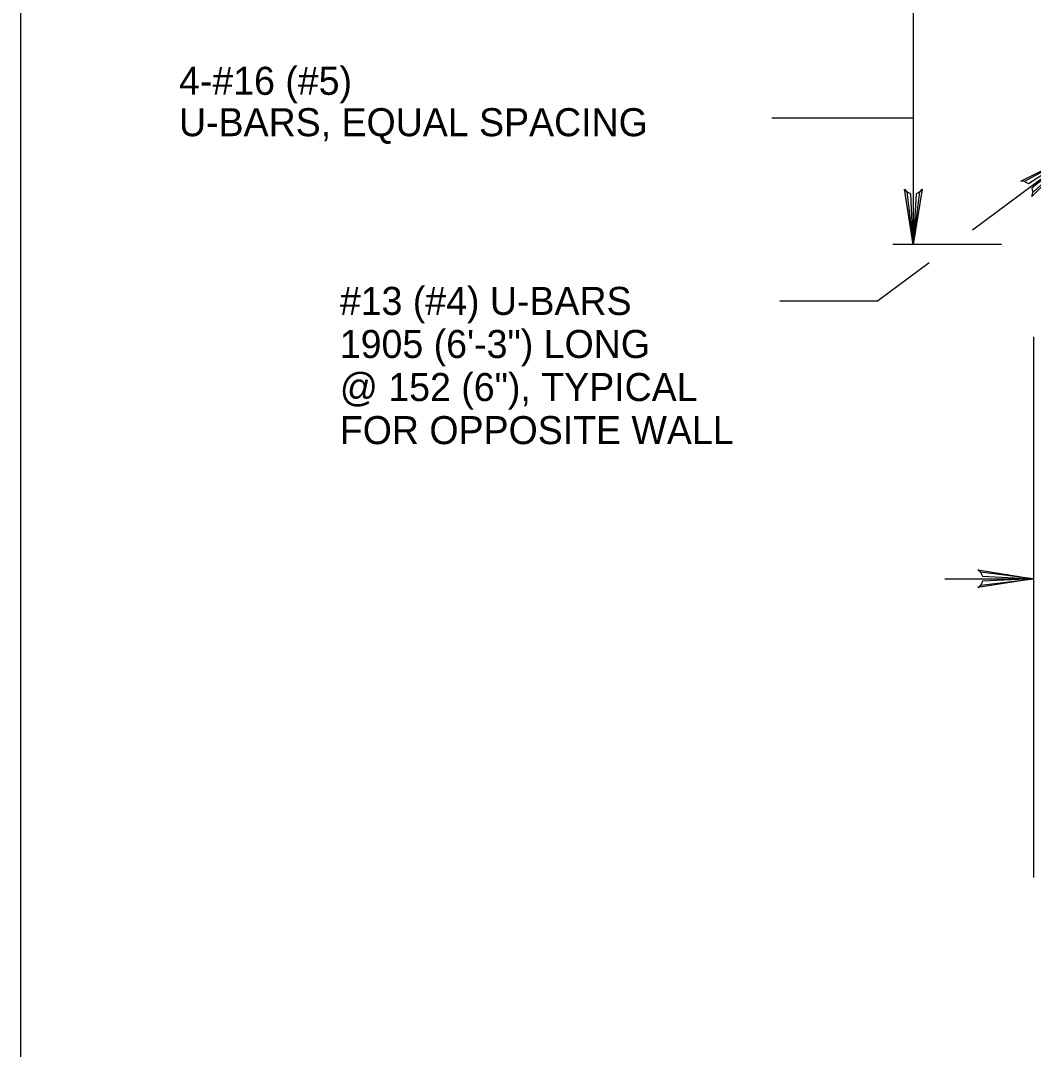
# Model space of a CAD drawing. Extents: x 638455 to 640199, y 298558 to 299152.
# Drawn here: x 639333.6 to 639455, y 298856.5 to 298979.8 of the extents above; entities that cross this region are included whole.
import ezdxf

# ---------------------------------------------------------------- set-up
doc = ezdxf.new("R2010")
doc.units = 0
for name, color, linetype in [('1', 7, 'Continuous'), ('2', 7, 'Continuous'), ('3', 7, 'Continuous')]:
    doc.layers.add(name, color=color, linetype=linetype)

msp = doc.modelspace()

# ---------------------------------------------------------------- linework, layer by layer
at = {"layer": '1'}
for points in [[(640119.61, 298573.25), (640119.61, 299137.25), (639333.61, 299137.25), (639333.61, 298573.25), (640119.61, 298573.25), (640119.61, 298599.61), (639919.61, 298599.61), (639919.61, 298664.29), (640119.61, 298664.29), (640119.61, 298693.25), (639919.61, 298693.25), (639919.61, 298573.25), (639998.42, 298573.25), (639998.42, 298599.61), (639998.42, 298573.25), (640075.42, 298573.25), (640075.42, 298599.61), (640075.42, 298587.29), (640119.61, 298587.29)], [(639453.92, 298960.48), (639454.41, 298960.24), (639459.83, 298963.74), (639453.92, 298960.48), (639453.47, 298960.52), (639459.83, 298963.74), (639454.81, 298959.69), (639454.9, 298959.17), (639459.83, 298963.74), (639454.8, 298958.69), (639454.9, 298959.17)]]:
    msp.add_lwpolyline(points, dxfattribs=at)
at = {"layer": '2'}
for p, q in [((639440.59, 299066.59), (639440.59, 298952.92)), ((639423.64, 298968.1), (639440.59, 298968.1)), ((639447.69, 298954.68), (639459.83, 298963.74)), ((639451.15, 298952.92), (639438.15, 298952.92)), ((639436.28, 298946.17), (639442.48, 298950.79)), ((639424.58, 298946.17), (639436.28, 298946.17)), ((639454.98, 298941.89), (639454.98, 298877.08)), ((639444.36, 298912.89), (639454.98, 298912.89))]:
    msp.add_line(p, q, dxfattribs=at)
for points in [[(639441.38, 298959.25), (639440.92, 298959.02), (639440.59, 298952.92), (639441.38, 298959.25), (639441.66, 298959.58), (639440.59, 298952.92), (639440.28, 298959.01), (639439.83, 298959.23), (639440.59, 298952.92), (639439.53, 298959.58), (639439.83, 298959.23)], [(639448.65, 298913.68), (639448.89, 298913.22), (639454.98, 298912.89), (639448.65, 298913.68), (639448.33, 298913.96), (639454.98, 298912.89), (639448.89, 298912.59), (639448.67, 298912.13), (639454.98, 298912.89), (639448.33, 298911.83), (639448.67, 298912.13)]]:
    msp.add_lwpolyline(points, dxfattribs=at)

# ---------------------------------------------------------------- texts
at = {"layer": '3'}
for s, p in [('4-#16 (#5)', (639352.6, 298970.87)), ('U-BARS, EQUAL SPACING', (639352.6, 298965.91)), ('#13 (#4) U-BARS', (639371.87, 298944.5)), ('1905 (6\'-3") LONG', (639371.87, 298939.34)), ('@ 152 (6"), TYPICAL', (639371.87, 298934.18)), ('FOR OPPOSITE WALL', (639371.87, 298929.02))]:
    msp.add_text(s, height=3.36, dxfattribs=at).set_placement(p)

doc.saveas('drawing.dxf')
